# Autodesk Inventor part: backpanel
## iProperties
Created: 2005-05
Part Number: backpanel
Material: cherry
Document SubType Name: Modeling
Designer: a.campbell
Manufacturer: Standard
Standards Organization: Custom
length: 457
thickness: 7
width: 320
Author: a.campbell
Comments: machine to detail
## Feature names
1. Extrusion1
